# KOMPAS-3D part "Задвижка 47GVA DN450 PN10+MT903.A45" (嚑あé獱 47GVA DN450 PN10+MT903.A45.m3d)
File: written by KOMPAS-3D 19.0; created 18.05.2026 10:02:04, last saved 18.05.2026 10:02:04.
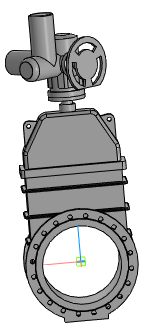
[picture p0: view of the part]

Document properties: Автор: Энергия; Полное имя файла: ..\Задвижка 47GVA DN50_DN1000+MT903.A\Задвижка 47GVA DN450 PN10+MT903.A45.a3d

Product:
- Part/product: Задвижка 47GVA DN450 PN10+MT903.A45
    Масса: 851.909
  - Body: Электропривод МТ903.А45 без блока управления
      Масса: 175.721
  - Body: Задвижка 47GVA DN450 PN10 без исполнительного механизма
      Масса: 676.188

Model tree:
1. Операция без истории:1
2. Операция без истории:2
